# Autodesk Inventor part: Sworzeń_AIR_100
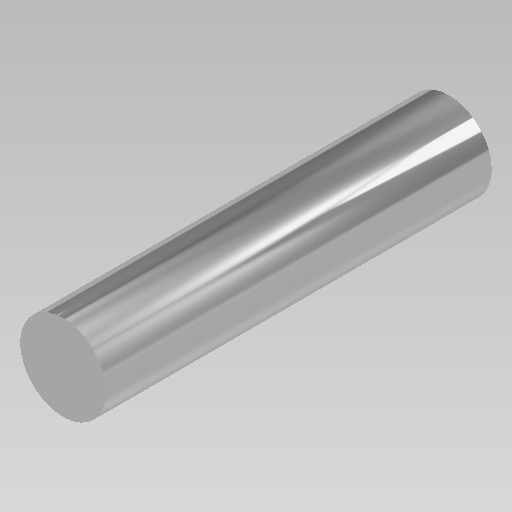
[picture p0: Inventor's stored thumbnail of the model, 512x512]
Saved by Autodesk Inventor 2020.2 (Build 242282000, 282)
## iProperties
Created: 2000-05
Part Number: Sworzeń_AIR_100
Document SubType Name: Modeling
Designer: F.Stasiak
Density: 7.85 g/cm^3
Material: Stal
Appearance: Chrom - polerowany
Mass: 221.954 g
Surface Area: 62.8319 cm^2
Volume: 28.2743 cm^3
Catalog Web Link: www.expertbooks.pl
Manager: www.cadconsulting.pl
Company: Fabian Stasiak CAD Consulting
Control State: 0
Master: False
Checked Out: False
Shininess: 0.0
Density: 0.0
Volumn: 0.0
Area: 0.0
PropertySet Name: Model Information
Author: F.Stasiak
Subject: Zbiór ćwiczeń. Autodesk Inventor 2020. Kurs Professional
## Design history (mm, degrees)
sketch "Szkic1"
  geometry: C1 r 10 at (0, 0); 1 further point
  constraints: 1 centre point, 1 coincident
  dimensions: "d3" = 20 diameter of C1
extrude "Wyciągnięcie proste1" new body sketch "Szkic1" stored distance "d4" = 90; taper "d5" = 0 deg
node "Punkt konstrukcyjny1"
node "Bryła2"
node "Korpusy bryłowe"
node "Korpusy powierzchniowe"
